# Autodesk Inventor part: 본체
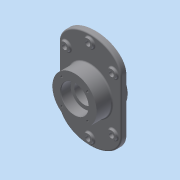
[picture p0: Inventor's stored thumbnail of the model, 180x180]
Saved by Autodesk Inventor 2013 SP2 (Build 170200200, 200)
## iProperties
Created: 2015-02
Part Number: 본체
Material: 일반
Document SubType Name: Modeling
Designer: dgall
Density: 1 g/cm^3
Author: dgall
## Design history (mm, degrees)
sketch "스케치1"
  geometry: L1 (-35, 0)-(35, 0); L2 (-35, 50)-(35, 50); L3 (-35, 31)-(-35, 0); L4 (-35, 50)-(-35, 0); L5 (-35, 50)-(-35, 31); L6 (35, 50)-(35, 0); L7 (-13, 22.5)-(13, 22.5); L8 (-35, 31)-(-13, 31); L9 (13, 31)-(35, 31); L10 (-13, 31)-(-13, 0); L11 (13, 31)-(13, 0); L12 (13, 21.815)-(13, 0); L13 (-13, 22.5)-(-13, 0); L14 (-13, 31)-(-13, 22.5); L15 (13, 31)-(13, 22.5); 2 further points
  constraints: 30 end point, 6 perpendicular, 5 point on line, 4 collinear, 2 coincident, 2 parallel, 2 vertical alignment, 1 horizontal, 1 midpoint
  dimensions: "d0" = 70 distance of L1.start L1.end; "d1" = 100 diameter of L2 L1; "d6" = 45 diameter of L7 L1; "d7" = 62 diameter of L9 L1; "d8" = 62 diameter of L8 L1; "d9" = 22 distance of L9.start L9.end; "d10" = 22 distance of L8.start L8.end
revolve "회전1" sketch "스케치1" stored, may be unused: angle "d11" = 90 deg
sketch "스케치5"
  geometry: L1 (-28.991, 28.991)-(0, 0); L2 (0, 0)-(-41, 0); C1 r 50 at (0, 0) reference; A1 r 41 centre (0, 0) between (-28.991, 28.991) and (-41, 0); 1 further point
  constraints: 4 end point, 2 coincident, 2 point on circle, 1 centre point, 1 horizontal
  dimensions: "d35" = 82 diameter of A1; "d37" = 45 deg angle of L2 L1
hole "구멍1" sketch "스케치5" at (-28.991, 28.991) diameter "d39" = 4.917; stored, may be unused: countersink angle "d43" = 90 deg, drill point angle "d45" = 118 deg; dims "d40" = 10, "d41" = 4, "d42" = 2, "d44" = 13
fillet "모깎기3" dims "d49" = 0.3
chamfer "모따기1" distance "d54" = 1; stored, may be unused: second distance "d55" = 2, angle "d56" = 45 deg
node "작업 평면6"
sketch "스케치17"
  geometry: L1 (-70, 110)-(70, 110); L2 (70, 110)-(70, -110); L3 (70, -110)-(-70, -110); L4 (-70, -110)-(-70, 110); 9 further points; 2 other entities
  constraints: 8 end point, 5 horizontal, 4 point on line, 3 vertical, 2 midpoint, 2 parallel, 1 horizontal alignment, 1 perpendicular, 1 vertical alignment, 9 other
  dimensions: "d122" = 140 distance of L1.start L1.end; "d124" = 220 distance of L1.end L2.end; "d125" = 50 distance from line of L1 point (0, 60); "d126" = 50 distance from line of L3 point (0, -60)
extrude "돌출15" join sketch "스케치17" distance "d127" = 12; taper "d128" = 0 deg
sketch "스케치18"
  geometry: L1 (-70, 60)-(-70, -60) reference; L2 (70, -60)-(70, 60) reference; L3 (-53, 60)-(-53, -60); L4 (53, -60)-(53, 60); C1 r 50 at (0, 0) reference; C2 r 10 at (53, 60); C3 r 10 at (-53, 60); C4 r 10 at (-53, -60); C5 r 10 at (0, -93); C6 r 10 at (53, -60); C7 r 10 at (0, 93); C8 r 5.5 at (53, 60); C9 r 5.5 at (0, 93); C10 r 5.5 at (53, -60); C11 r 5.5 at (0, -93); C12 r 5.5 at (-53, -60); C13 r 5.5 at (-53, 60); 2 further points; 2 other entities
  constraints: 12 centre point, 5 equal radius, 4 coincident, 4 end point, 3 parallel, 2 vertical alignment, 10 other
  dimensions: "d129" = 17 distance between parallel lines of L2 L4; "d131" = 20 diameter of C2; "d132" = 20 diameter of C3; "d133" = 20 diameter of C4; "d135" = 20 diameter of C5; "d136" = 20 diameter of C6; "d137" = 20 diameter of C7; "d140" = 11 diameter of C9
extrude "돌출16" join sketch "스케치18" distance "d138" = 5; taper "d139" = 0 deg
extrude "돌출17" cut sketch "스케치18" stored distance "d141" = 5; taper "d142" = 0 deg
sketch "스케치19"
  geometry: C1 r 22.5 at (0, 0) reference
extrude "돌출18" cut sketch "스케치19" stored distance "d143" = 5; taper "d144" = 0 deg
fillet "모깎기15" dims "d145" = 3
fillet "모깎기16" dims "d146" = 3
fillet "모깎기17" dims "d147" = 3
node "솔리드1"
pattern_circular "원형 패턴1" dims angle "d47" = 360 deg
mirror "대칭1"
other parameters: "d121" = -23
